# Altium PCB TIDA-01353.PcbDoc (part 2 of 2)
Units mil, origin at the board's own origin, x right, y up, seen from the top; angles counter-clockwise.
Board outline 6000 x 6000 mil, 2 copper layers (Top Layer, Bottom Layer), stack 61.6 mil thick; 250 components, 122 nets, 562 pads, 165 vias.
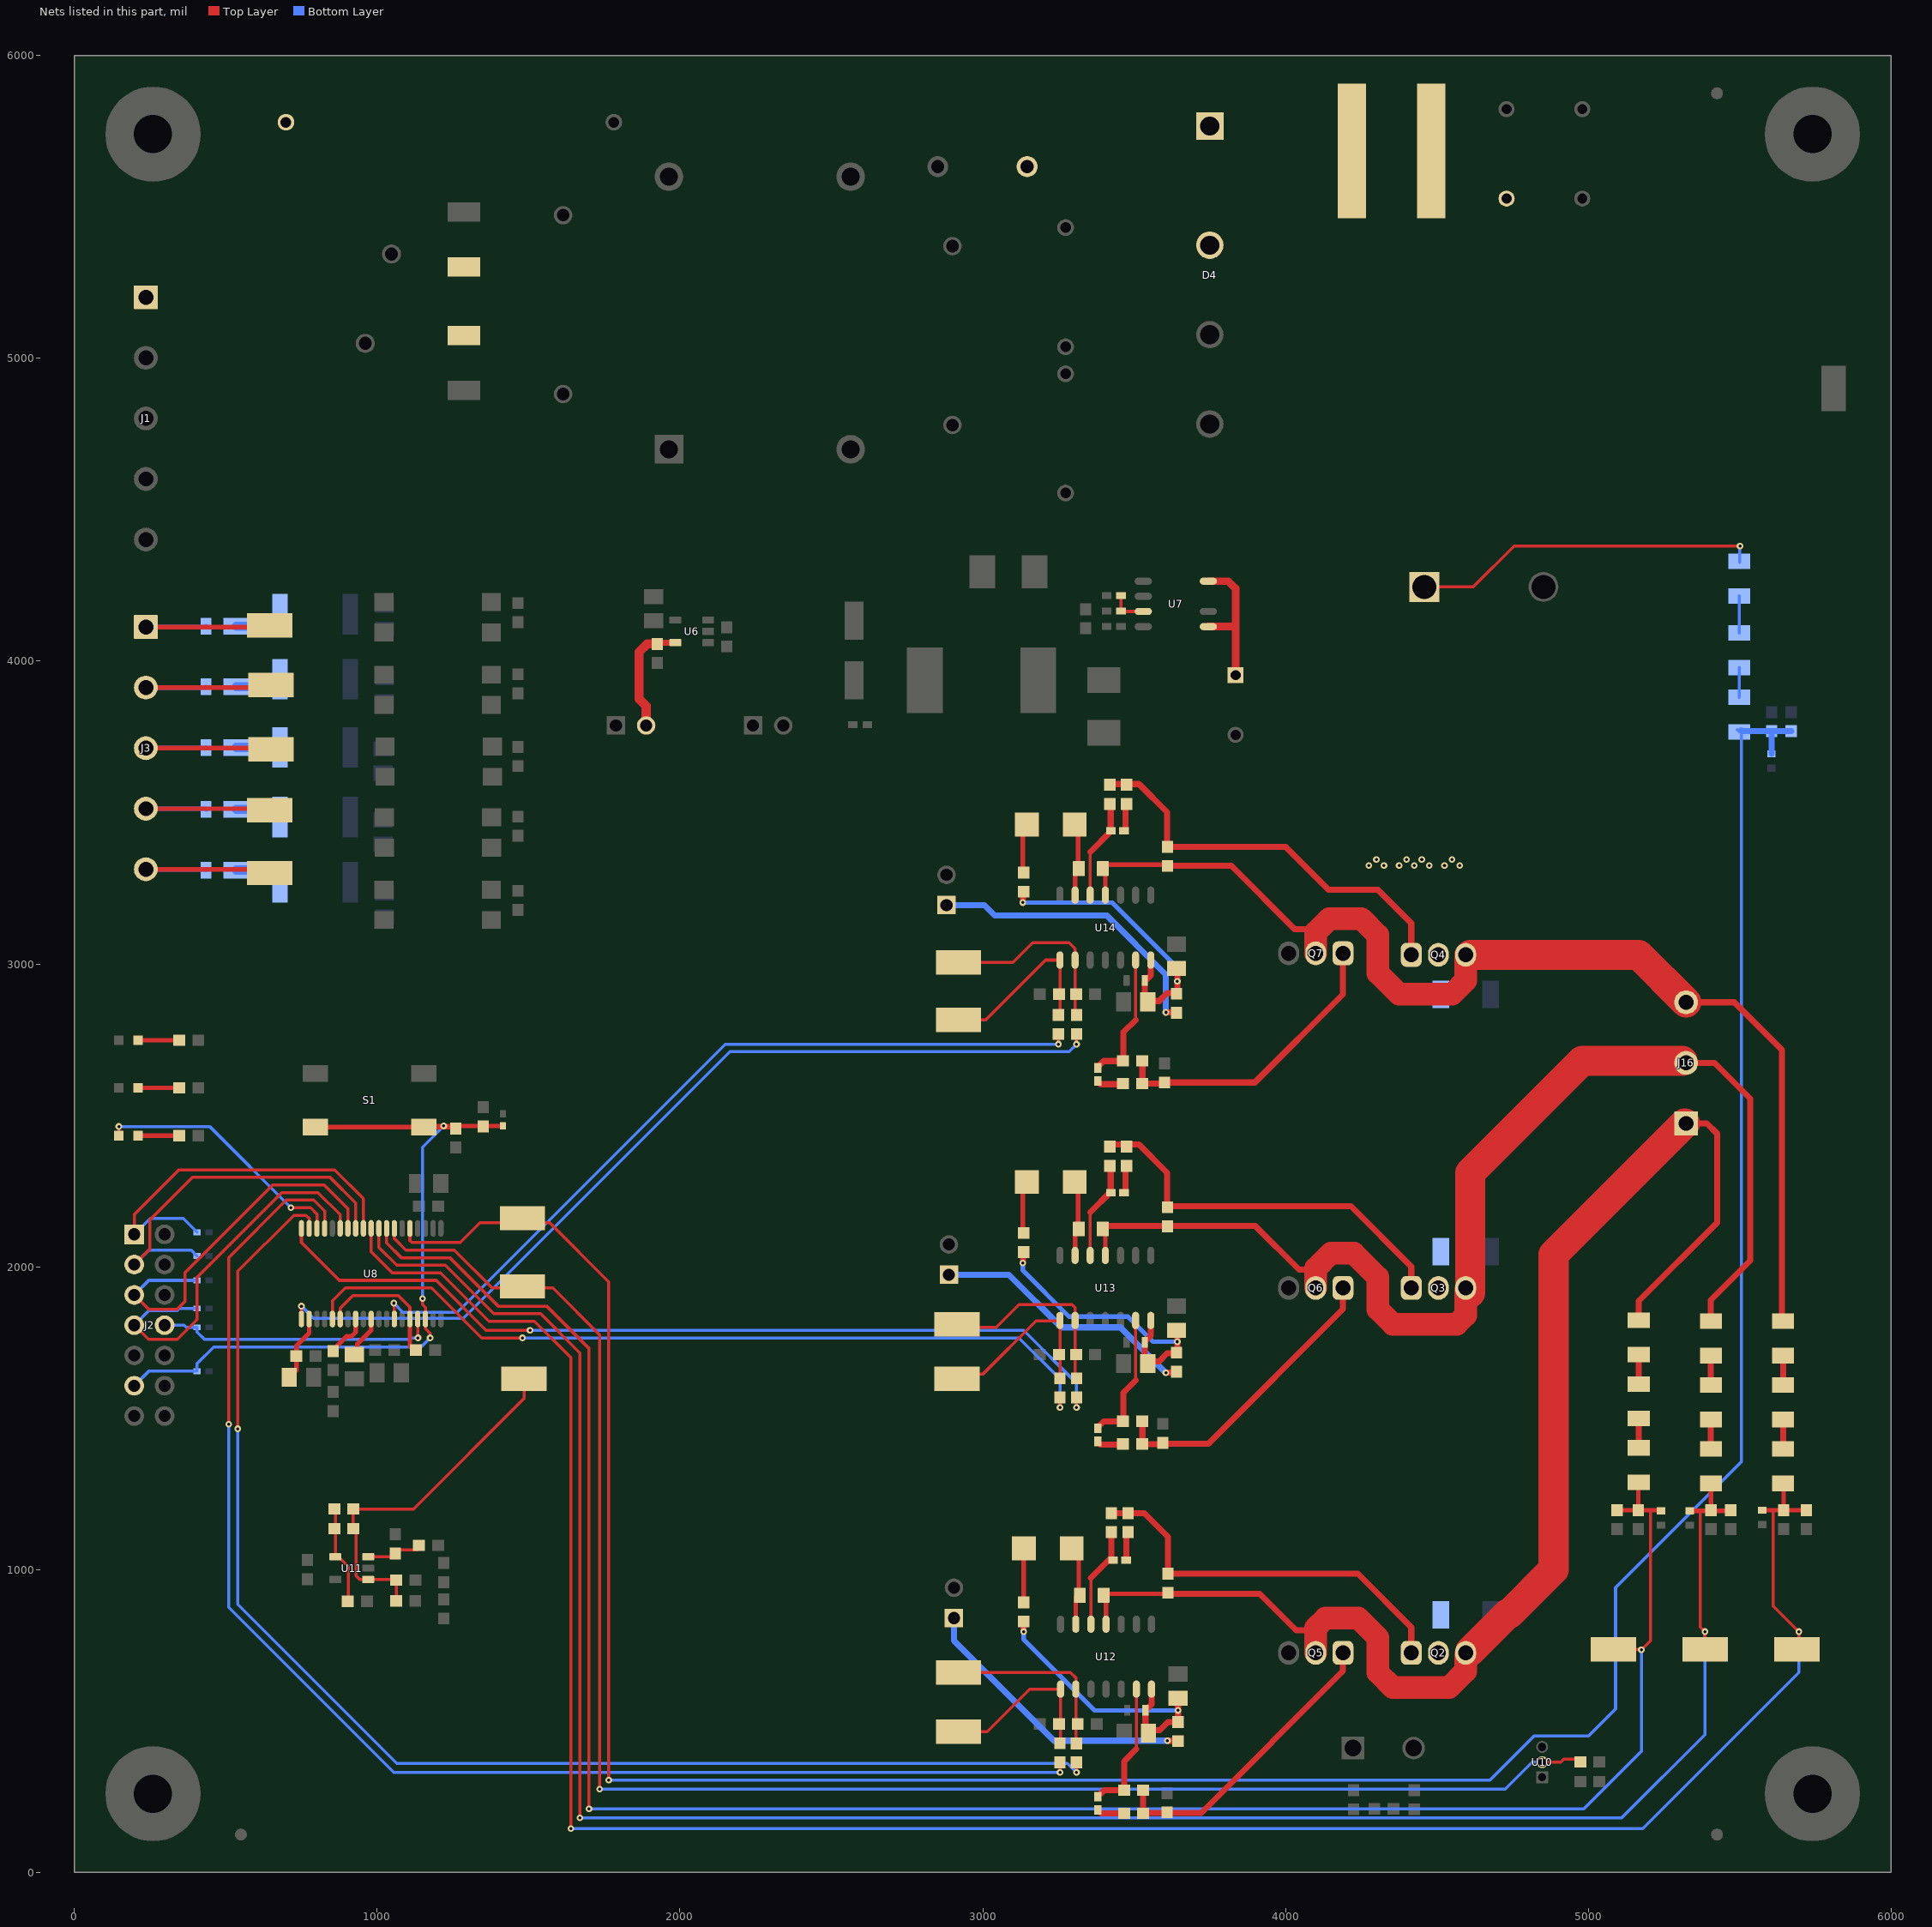
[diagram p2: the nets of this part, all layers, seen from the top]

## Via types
v1: diameter 22, hole 10, Top Layer to Bottom Layer, tented both sides, 165 vias

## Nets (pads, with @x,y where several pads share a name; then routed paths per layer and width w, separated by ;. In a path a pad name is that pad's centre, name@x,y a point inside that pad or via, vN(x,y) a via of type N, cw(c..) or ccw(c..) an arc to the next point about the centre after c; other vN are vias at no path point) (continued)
NetC19_1: C19.1 J4.2 U6.5 | length 385.1
  Top Layer w10: C19.1@1925,4056.5 C19.1@1929.53,4061.02
  Top Layer w20: C19.1@1929.53,4061.02 U6.5@1984.93,4061.02
  Top Layer w30: J4.2@1888.58,3787.4 1888.58,3851.42 1865,3875 1865,4030 1891.5,4056.5 C19.1@1925,4056.5
NetC26_1: C26.1 U8.29 | length 131.2
  Top Layer w15: C26.1@935,1715 935,1745 980.32,1790.32 U8.29@980.32,1827.44
NetC27_1: C27.1 C28.1 U8.21 | length 219.6
  Top Layer w15: C27.1@710,1635 733.5,1658.5 733.5,1738.5 775.59,1780.59 U8.21@775.59,1827.44
NetC37_1: C37.1 R34.1 R44.2 R55.2 TP17.1 U11.1 | length 1212.2
  Top Layer w10: R44.2@1063.07,896.65 1063.5,897.09 R55.2@1063.5,965 1061.17,967.33 U11.1@970.5,967.33 942.67,967.33 930,980 930,1127.68 920.31,1137.36 920.31,1195.31 925,1200 1120,1200 1485,1565 1485,1625.24 TP17.1@1480.31,1629.92
NetC37_2: C37.2 R34.2 R45.2 U11.4 | length 333.9
  Top Layer w10: R34.2@862.23,1211.19 862.23,1052.77 905,1010 R45.2@905,895
NetC46_1: C46.1 C50.1 C56.2 R56.1 R58.1 U12.7 | length 995.6
  Top Layer w15: C50.1@3537.32,480 C50.1@3547.32,470
  Top Layer w20: v1(3135,795) R56.1@3135,828.5 ; C50.1@3537.32,480 C46.1@3537.32,535 3557.32,555 U12.7@3557.32,605.16 ; C50.1@3547.32,470 3585,470 3611.5,496.5 R58.1@3645,496.5 C56.2@3645,570
  Bottom Layer w15: v1(3135,795) 3135,770 3370,535 v1(3645,535)
NetC47_1: C47.1 C51.1 C57.2 R57.1 R59.1 U13.7 | length 981.4
  Top Layer w20: v1(3132.68,2012.56) R57.1@3132.68,2046.06 ; C51.1@3535,1697.56 3535,1752.56 3555,1772.56 U13.7@3555,1822.72 ; C51.1@3545,1687.56 3582.68,1687.56 3609.18,1714.06 3642.68,1714.06 C57.2@3642.68,1787.56
  Bottom Layer w15: v1(3132.68,2012.56) 3132.68,1987.56 3285.24,1835 3480,1835 3562.44,1752.56 v1(3642.68,1752.56)
NetC48_1: C48.1 D20.1 U12.13 | length 272.9
  Top Layer w15: D20.1@3293.82,1078.74 3317.32,1055.24 3317.32,920 3307.32,910 U12.13@3307.32,819.72
NetC49_1: C49.1 D21.1 U13.13 | length 225.5
  Top Layer w15: U13.13@3305,2037.28 C49.1@3305,2127.56 ; C49.1@3315,2137.56 D21.1@3315,2272.8
NetC52_1: C52.1 R62.2 TP25.1 U12.1 | length 575
  Top Layer w10: TP25.1@2920,465 3015,465 3155.16,605.16 U12.1@3257.32,605.16 3257.32,428.81 R62.2@3255,426.5
NetC53_1: C53.1 R63.2 TP26.1 U13.1 | length 610.6
  Top Layer w10: TP26.1@2915,1630 2930,1645 3000,1645 3176.54,1821.54 U13.1@3255,1821.54 ; R63.2@3255,1631.5 U13.1@3255,1821.54 ; U13.1@3255,1822.72 U13.1@3255,1821.54
NetC54_1: C54.1 R68.2 TP29.1 U12.2 | length 618
  Top Layer w10: TP29.1@2920,645 2935,660 3290,660 3307.32,642.68 U12.2@3307.32,605.16 3307.32,428.53 R68.2@3309.57,426.28
NetC55_1: C55.1 R69.2 TP32.1 U13.2 | length 660.8
  Top Layer w10: TP32.1@2915,1800 3045,1800 3120,1875 3295,1875 3305,1865 U13.2@3305,1822.72 3305,1636.5 R69.2@3310,1631.49
NetC58_1: C58.1 C60.1 C66.2 R76.1 R77.1 U14.7 | length 993
  Top Layer w20: v1(3132.68,3202.56) R76.1@3132.68,3236.06 ; C60.1@3535,2887.56 3535,2942.56 3555,2962.56 U14.7@3555,3012.72 ; C60.1@3545,2877.56 3582.68,2877.56 3609.18,2904.06 3642.68,2904.06 C66.2@3642.68,2977.56
  Bottom Layer w15: v1(3132.68,3202.56) 3427.44,3202.56 3642.68,2987.32 v1(3642.68,2942.56)
NetC59_1: C59.1 D26.1 U14.13 | length 225.5
  Top Layer w15: U14.13@3305,3227.28 C59.1@3305,3317.56 ; C59.1@3315,3327.56 D26.1@3315,3462.8
NetC64_1: C64.1 R79.2 TP35.1 U14.1 | length 606.9
  Top Layer w10: TP35.1@2920,2815 3010,2815 3207.72,3012.72 U14.1@3255,3012.72 ; R79.2@3255,2821.5 U14.1@3255,3011.54
NetC65_1: C65.1 R82.2 TP37.1 U14.2 | length 643.7
  Top Layer w10: TP37.1@2920,3005 3100,3005 3165,3070 3285,3070 3305,3050 U14.2@3305,3012.72 R82.2@3305,2826.5
NetD1_1: D1.1 R2.1 | length 139.8
  Bottom Layer w30: D1.1@535.2,3310 R2.1@675,3310
NetD2_1: D2.1 R4.1 | length 139.8
  Bottom Layer w30: D2.1@535.2,3510 R4.1@675,3510
NetD3_1: D3.1 R7.1 | length 143.7
  Bottom Layer w30: D3.1@535.2,3715 R7.1@678.86,3715
NetD4_1: D4.1 L1.1
NetD4_2: D4.2 RT1.2
NetD5_1: D5.1 R10.1 | length 139.8
  Bottom Layer w30: D5.1@535.2,3915 R10.1@675,3915
NetD6_1: D6.1 R12.1 | length 139.8
  Bottom Layer w30: D6.1@535.2,4115 R12.1@675,4115
NetD13_1: D13.1 U8.17 | length 855.5
  Top Layer w10: v1(147.05,2463.19) D13.1@147.05,2433.07 D13.1@150,2430.12 ; v1(715,2195) 780,2195 801.18,2173.82 U8.17@801.18,2126.66
  Bottom Layer w10: v1(147.05,2463.19) 446.81,2463.19 v1(715,2195)
NetD13_2: D13.2 R26.2 | length 136.4
  Top Layer w15: D13.2@210.04,2433.07 R26.2@346.46,2433.07
NetD14_2: D14.2 R29.1 | length 136.4
  Top Layer w15: D14.2@210.04,2748.03 R29.1@346.46,2748.03
NetD15_2: D15.2 R27.2 | length 136.4
  Top Layer w15: D15.2@210.04,2590.55 R27.2@346.46,2590.55
NetD20_2: D20.2 R56.2 | length 187.8
  Top Layer w15: R56.2@3135,891.5 3135,1077.4 D20.2@3136.34,1078.74
NetD21_2: D21.2 R57.2 | length 185.9
  Top Layer w15: R57.2@3132.68,2109.06 D21.2@3132.68,2294.96
NetD22_1: D22.1 R60.1 U12.12 | length 331.8
  Top Layer w10: U12.12@3357.32,819.72 3357.32,972.32
  Top Layer w20: 3357.32,972.32 3425,1040 R60.1@3425,1123.5
NetD22_2: D22.2 R64.1 | length 95
  Top Layer w10: R64.1@3473.75,1117.25 R64.1@3480,1123.5
  Top Layer w20: D22.2@3473.75,1031.11 R64.1@3473.75,1117.25
NetD23_1: D23.1 R61.1 U13.12 | length 331.8
  Top Layer w10: U13.12@3355,2037.28 3355,2179.87
  Top Layer w20: 3355,2179.87 3422.68,2247.56 R61.1@3422.68,2341.06
NetD23_2: D23.2 R65.1 | length 86.1
  Top Layer w20: D23.2@3471.43,2248.67 R65.1@3471.43,2334.81
NetD24_1: D24.1 R72.1 U12.6 | length 442.9
  Top Layer w10: 3507.32,407.32 U12.6@3507.32,605.16
  Top Layer w20: D24.1@3379.84,250 3401.5,271.65 R72.1@3466.84,271.65 ; R72.1@3466.84,275 3466.84,366.84 3507.32,407.32
NetD24_2: D24.2 R70.1 | length 91.8
  Top Layer w20: D24.2@3379.84,206.69 3391.32,195.22 R70.1@3466.84,195.22
NetD25_1: D25.1 R73.1 U13.6 | length 442.9
  Top Layer w10: 3505,1624.88 U13.6@3505,1822.72
  Top Layer w20: D25.1@3377.53,1467.56 3399.18,1489.21 R73.1@3464.53,1489.21 ; R73.1@3464.53,1492.56 3464.53,1584.4 3505,1624.88
NetD25_2: D25.2 R71.1 | length 91.8
  Top Layer w20: D25.2@3377.53,1424.25 3389,1412.78 R71.1@3464.53,1412.78
NetD26_2: D26.2 R76.2 | length 185.9
  Top Layer w15: R76.2@3132.68,3299.06 D26.2@3132.68,3484.96
NetD27_1: D27.1 R78.1 U14.12 | length 331.8
  Top Layer w10: U14.12@3355,3227.28 3355,3369.88
  Top Layer w20: 3355,3369.88 3422.68,3437.56 R78.1@3422.68,3531.06
NetD27_2: D27.2 R80.1 | length 86.1
  Top Layer w20: D27.2@3471.43,3438.67 R80.1@3471.43,3524.81
NetD28_1: D28.1 R84.1 U14.6 | length 442.9
  Top Layer w10: 3505,2814.88 U14.6@3505,3012.72
  Top Layer w20: D28.1@3377.53,2657.56 3399.18,2679.21 R84.1@3464.53,2679.21 ; R84.1@3464.53,2682.56 3464.53,2774.4 3505,2814.88
NetD28_2: D28.2 R83.1 | length 91.8
  Top Layer w20: D28.2@3377.53,2614.25 3389,2602.78 R83.1@3464.53,2602.78
NetF1_2: F1.2 J1.1
NetJ12_1: J12.1 R58.2 | length 952.3
  Top Layer w10: v1(3610,435) v1@3611.5,433.5
  Top Layer w20: v1(3610,435) R58.2@3643.5,435
  Bottom Layer w20: J12.1@2905,840 2905,765 3235,435 v1(3610,435)
NetJ13_1: J13.1 R59.2 | length 887.2
  Top Layer w10: R59.2@3636.49,1650 R59.2@3640,1653.5
  Top Layer w20: v1(3605,1650) R59.2@3636.49,1650
  Bottom Layer w20: J13.1@2888.31,1973.62 3086.38,1973.62 3260,1800 3455,1800 v1(3605,1650)
NetJ15_1: J15.1 R77.2 | length 978
  Top Layer w20: v1(3605,2840) R77.2@3638.5,2840
  Bottom Layer w20: J15.1@2880.43,3194.09 3005.91,3194.09 3040,3160 3410,3160 3605,2965 v1(3605,2840)
NetR5_1: R5.1 R8.2
NetR13_1: R13.1 R14.2 U7.3 | length 125.4
  Top Layer w10: R14.2@3456.69,4216.54 R13.1@3456.69,4165.35 3458.07,4163.98 U7.3@3530.33,4163.98
NetR32_1: R32.1 U8.27 | length 148.4
  Top Layer w15: R32.1@850,1721.5 898.5,1770 915,1770 929.13,1784.14 U8.27@929.13,1827.44
NetR35_1: R35.1 R41.2 | length 96.8
  Top Layer w20: R41.2@5166.73,1612.94 R35.1@5166.73,1709.71
NetR36_1: R36.1 R42.2 | length 96.8
  Top Layer w20: R42.2@5404.69,1609.73 R36.1@5404.69,1706.5
NetR37_1: R37.1 R43.2 | length 96.8
  Top Layer w20: R43.2@5643.3,1609.73 R37.1@5643.3,1706.5
NetR38_1: R38.1 R40.2 | length 122
  Bottom Layer w10: R40.2@5498.35,4093.11 R38.1@5498.35,4215.16
NetR39_2: R39.2 R50.2 U11.3 | length 172.1
  Top Layer w10: U11.3@970.5,1042.14 1044.26,1042.14 R50.2@1060.74,1058.62 ; R50.2@1060,1065 R39.2@1135,1065
NetR40_1: R40.1 R46.2 | length 98.4
  Bottom Layer w10: R46.2@5498.35,3880.51 R40.1@5498.35,3978.94
NetR41_1: R41.1 R47.2 | length 96.8
  Top Layer w20: R47.2@5166.73,1401.99 R41.1@5166.73,1498.77
NetR42_1: R42.1 R48.2 | length 96.8
  Top Layer w20: R48.2@5404.69,1398.78 R42.1@5404.69,1495.55
NetR43_1: R43.1 R49.2 | length 96.8
  Top Layer w20: R49.2@5643.3,1398.78 R43.1@5643.3,1495.55
NRST: C24.1 J2.11 R30.1 S1.3 S1.4 U8.36 U15.1 U20.2 | length 2502.3
  Top Layer w10: v1(1150,1895) 1150,1875 1159.45,1865.55 U8.36@1159.45,1827.44 1159.45,1795.55 1175,1780 v1(1175,1765)
  Top Layer w15: S1.3@780,2461.42 S1.3@795.87,2461.42 S1.4@1154.13,2461.42 R30.1@1249.13,2461.42 ; S1.4@1170.39,2465 v1(1220,2465) C24.1@1345,2465 ; C24.1@1353.03,2465 U20.2@1415,2465
  Bottom Layer w10: J2.11@198.03,1607.09 245.95,1655 U15.1@405.32,1655 405.32,1680.32 460,1735 1145,1735 v1(1175,1765) ; v1(1150,1895) 1150,2395 v1(1220,2465)
OC_FLT: R31.2 U8.25 U8.34 | length 447.1
  Top Layer w10: U8.25@877.95,1827.44 877.95,1862.95 920,1905 1070,1905 1108.27,1866.73 U8.34@1108.27,1827.44
  Top Layer w15: U8.34@1108.27,1827.44 1108.27,1738.19 R31.2@1122.05,1724.41
PHU: C48.2 J16.1 Q2.3 Q5.2 R35.2 R66.1 U12.11 | length 4556.9
  Top Layer w15: U12.11@3407.32,819.72 3407.32,910 3397.32,920 R66.1@3611.49,920
  Top Layer w20: R66.1@3611.5,920 3915,920 4035,800 4095,800 ; R35.2@5166.73,1823.89 5166.73,1886.73 5425,2145 5425,2440 5391.77,2473.23 J16.1@5322.83,2473.23
  Top Layer w75: Q5.2@4100,725 4100,808 4132,840 4240,840 4305,775 4305,660 4355,610 4540,610 4594.76,664.76 Q2.3@4594.76,720
  Top Layer w100: Q2.3@4610,730 4735,855 ; 4740,855 4885,1000 4885,2040 J16.1@5318.23,2473.23
PHU_FB: C41.1 D16.2 R47.1 R51.2 TP19.1 U8.8 | length 7075.1
  Top Layer w10: U8.8@1031.5,2126.66 1031.5,2078.5 1080,2030 1240,2030 1400,1870 1560,1870 1700,1730 v1(1700,210) ; TP19.1@5082.68,736.65 5176.65,736.65 5205,765 5205,1196.02
  Top Layer w15: C41.1@5091.93,1196.02 5239.53,1196.02 D16.2@5240,1196.5 ; R51.2@5165,1196.5 5165,1286.09 R47.1@5166.73,1287.82
  Bottom Layer w10: v1(1700,210) 4985,210 5175,400 v1(5175,735)
PHV: C49.2 J16.2 Q3.3 Q6.2 R36.2 R67.1 U13.11 | length 3971
  Top Layer w15: U13.11@3405,2037.28 C49.2@3405,2127.56
  Top Layer w20: C49.2@3395,2135 3900,2135 4045,1990 4080,1990 ; J16.2@5322.83,2673.23 5416.77,2673.23 5535,2555 5535,2020 5404.69,1889.69 R36.2@5404.69,1820.67
  Top Layer w75: Q6.2@4100,1930 4100,1995 4150,2045 4225,2045 4305,1965 4305,1860 4355,1810 4565,1810 4594.76,1839.76 Q3.3@4594.76,1925
  Top Layer w100: Q3.3@4610,1915 4610,2310 4980,2680 J16.2@5311.06,2680
PHV_FB: C42.1 D17.2 R48.1 R52.2 TP20.1 U8.9 | length 7263.1
  Top Layer w10: U8.9@1005.91,2126.66 1005.91,2064.09 1065,2005 1225,2005 1385,1845 1540,1845 1670,1715 v1(1670,180) ; 5370,1193.62 5370,810 5385.83,794.17 TP20.1@5385.83,736.65
  Top Layer w15: D17.2@5335,1193.62 5467.12,1193.62 C42.1@5470,1196.5 ; R48.1@5404.69,1284.61 5405,1284.29 R52.2@5405,1196.5
  Bottom Layer w10: v1(1670,180) 5110,180 5385,455 v1(5385,795)
PHW: C59.2 J16.3 Q4.3 Q7.2 R37.2 R81.1 U14.11 | length 3872.1
  Top Layer w15: C59.2@3395,3327.56 3546.18,3327.56 3607.44,3327.56 R81.1@3611,3324 ; U14.11@3405,3227.28 C59.2@3405,3317.56 ; Q7.2@4100,3045 4100,3115
  Top Layer w20: R81.1@3611,3324 3821,3324 4030,3115 4100,3115 ; J16.3@5322.83,2873.23 5481.77,2873.23 5640,2715 R37.2@5640,1820.67
  Top Layer w75: Q7.2@4100,3035 4100,3105 4145,3150 4250,3150 4305,3095 4305,2970 4375,2900 4550,2900 4594.76,2944.76 Q4.3@4594.76,3030
  Top Layer w100: Q4.3@4610,3030 5166.06,3030 J16.3@5322.83,2873.23
PHW_FB: C43.1 D18.2 R49.1 R53.2 TP21.1 U8.10 | length 7571.9
  Top Layer w10: U8.10@980.32,2126.66 980.32,2049.68 1050,1980 1210,1980 1370,1820 1520,1820 1640,1700 v1(1640,145) ; 5610,1196.02 5610,880 v1(5695,795) 5695,742.68 TP21.1@5688.98,736.65
  Top Layer w15: D18.2@5573.97,1196.02 5719.53,1196.02 C43.1@5720,1196.5 ; R49.1@5643.3,1284.61 5645,1282.91 R53.2@5645,1196.5
  Bottom Layer w10: v1(1640,145) 5180,145 5695,660 v1(5695,795)
PWM_UB: R68.1 U8.18 | length 4487.7
  Top Layer w10: v1(540,1465) 540,1985 725,2170 765,2170 775.59,2159.41 U8.18@775.59,2126.66 ; R68.1@3309.57,363.29 3309.57,330.43 v1(3310,330)
  Bottom Layer w10: v1(540,1465) 540,885 1065,360 3280,360 v1(3310,330) v1@3310,325
PWM_UT: R62.1 U8.16 | length 4626.5
  Top Layer w10: v1(510,1480) 510,2030 700,2220 790,2220 826.77,2183.23 U8.16@826.77,2126.66 ; v1(3255,330) R62.1@3255,363.51
  Bottom Layer w10: v1(510,1480) 510,875 1055,330 v1(3255,330)
PWM_VB: R69.1 U8.19 | length 2917.8
  Top Layer w10: U8.19@750,2126.66 750,2080 875,1955 1195,1955 1360,1790 v1(1505,1790) ; v1(3310,1535) R69.1@3310,1568.5
  Bottom Layer w10: v1(1505,1790) 3135,1790 3310,1615 v1(3310,1535) v1@3310,1530
PWM_VT: R63.1 U8.24 | length 2738
  Top Layer w10: U8.24@852.36,1827.44 852.36,1887.36 895,1930 1180,1930 1345,1765 v1(1480,1765) ; v1(3255,1535) R63.1@3255,1568.5
  Bottom Layer w10: v1(1480,1765) 3120,1765 3255,1630 v1(3255,1535) v1@3255,1530
PWM_WB: R82.1 U8.20 | length 3027.5
  Top Layer w10: U8.20@750,1827.44 v1(750,1870) ; v1(3310,2735) R82.1@3310,2768.5
  Bottom Layer w10: v1(750,1870) 790,1830 1285,1830 2165,2710 3285,2710 v1(3310,2735)
PWM_WT: R79.1 U8.32 | length 2660.9
  Top Layer w10: v1(1055,1880) 1057.09,1877.91 U8.32@1057.09,1827.44 ; v1(3250,2735) R79.1@3250,2768.5
  Bottom Layer w10: v1(1055,1880) 1085,1850 1265,1850 2150,2735 v1(3250,2735)
SIGNAL_PIN1: D6.2 J3.1 TP5.1 | length 603.5
  Top Layer w15: J3.1@236.22,4112.6 TP5.1@640.16,4112.6
  Bottom Layer w15: J3.1@236.22,4112.6 432.4,4112.6 D6.2@434.8,4115
SIGNAL_PIN2: D5.2 J3.2 TP6.1 | length 604.3
  Top Layer w15: J3.2@236.22,3912.6 TP6.1@640.94,3912.6
  Bottom Layer w15: J3.2@236.22,3912.6 432.4,3912.6 D5.2@434.8,3915
SIGNAL_PIN3: D3.2 J3.3 TP7.1 | length 609
  Top Layer w15: J3.3@236.22,3712.6 TP7.1@645.67,3712.6
  Bottom Layer w15: J3.3@236.22,3712.6 432.4,3712.6 D3.2@434.8,3715
SIGNAL_PIN4: D2.2 J3.4 TP8.1 | length 604.4
  Top Layer w15: J3.4@236.22,3512.6 TP8.1@640.95,3512.6
  Bottom Layer w15: J3.4@236.22,3512.6 432.2,3512.6 D2.2@434.8,3510
SIGNAL_PIN5: D1.2 J3.5 TP9.1 | length 580.8
  Top Layer w15: J3.5@236.22,3312.6 TP9.1@617.4,3312.6
  Bottom Layer w15: J3.5@236.22,3312.6 432.2,3312.6 D1.2@434.8,3310
TCK: J2.7 U8.14 U16.1 | length 1288.2
  Top Layer w10: J2.7@198.03,1807.09 245.12,1760 340,1760 405,1825 405,1965 685,2245 805,2245 877.95,2172.05 U8.14@877.95,2126.66
  Bottom Layer w10: J2.7@198.03,1807.09 245.95,1855 340,1855 347.2,1862.2 U16.1@405.51,1862.2
TDI: J2.3 U8.12 U18.1 | length 1261.1
  Top Layer w10: J2.3@198.03,2007.09 250,2059.05 250,2155 390,2295 845,2295 929.13,2210.86 U8.12@929.13,2126.66
  Bottom Layer w10: J2.3@198.03,2007.09 245.95,2055 385.94,2055 U18.1@405.51,2035.43
TDO: J2.1 U8.11 U19.1 | length 1269.8
  Top Layer w10: J2.1@198.03,2107.09 198.03,2173.03 345,2320 860,2320 954.72,2225.28 U8.11@954.72,2126.66
  Bottom Layer w10: J2.1@198.03,2107.09 250.95,2160 359.69,2160 U19.1@405.51,2114.17
TEMP_SENSE: C36.2 TP15.1 U8.7 U10.2 | length 5626.8
  Top Layer w10: U8.7@1057.09,2126.66 1057.09,2092.91 1095,2055 1255,2055 1380,1930 1580,1930 1735,1775 v1(1735,275) ; U10.2@4847.44,364.25 4909.25,364.25 4918.76,373.76 C36.2@4977.51,373.76
  Bottom Layer w10: v1(1735,275) 4695,275 4725,275 4814.25,364.25 U10.2@4847.44,364.25
TEST: J2.8 U8.35 U9.1 | length 927.5
  Top Layer w10: U8.35@1133.86,1827.44 1133.86,1776.14 v1@1140,1770
  Bottom Layer w10: J2.8@298.03,1807.09 362.91,1807.09 370,1800 U9.1@405.32,1800 405.32,1784.68 430,1760 1105,1760 1110,1765 v1(1135,1765)
TMS: J2.5 U8.13 U17.1 | length 1275
  Top Layer w10: J2.5@198.03,1907.09 245.12,1860 340,1860 365,1885 365,1980 655,2270 825,2270 903.55,2191.45 U8.13@903.55,2126.66
  Bottom Layer w10: J2.5@198.03,1907.09 245.95,1955 U17.1@405.32,1955
UB: Q5.1 R70.2 R72.2 R74.2 | length 991.1
  Top Layer w20: R72.2@3529.84,271.65 R70.2@3529.84,195.22 3531.47,196.85 3721.85,196.85 4189.76,664.76 Q5.1@4189.76,725
UT: Q2.1 R60.2 R64.2 R66.2 | length 1297.5
  Top Layer w20: R60.2@3425,1186.5 R64.2@3480,1186.5 3533.5,1186.5 3611.5,1108.5 R66.2@3611.49,986.5 4238.5,986.5 4415.24,809.76 Q2.1@4415.24,730
VB: Q6.1 R71.2 R73.2 R75.2 | length 989.5
  Top Layer w20: R71.2@3527.52,1412.78 R73.2@3527.52,1489.21 ; R71.2@3529.15,1414.41 R75.2@3606.47,1414.41 ; R75.2@3608.51,1415 3745,1415 4189.76,1859.76 Q6.1@4189.76,1930
VDC_FB: C44.1 D19.2 R46.1 R54.2 TP22.1 U8.5 | length 9529.4
  Top Layer w10: U8.5@1108.27,2126.66 1108.27,2086.73 1115,2080 1275,2080 1340,2145 1570,2145 1765,1950 v1(1765,305)
  Bottom Layer w10: v1(1765,305) 4675,305 4820,450 5000,450 5090,540 5090,940 5505,1355 R46.1@5505,3771.65 ; R46.1@5491.18,3773.5 R46.1@5498.35,3766.34
  Bottom Layer w20: R46.1@5505,3771.65 5508.15,3768.5 C44.1@5670,3768.5 ; D19.2@5605,3693.62 R54.2@5605,3768.5
VDC_LINK: C3.1 C7.1 C17.1 C61.1 C62.1 C63.1 L1.2 Q2.2 Q3.2 Q4.2 R38.2 U7.5 U7.8 | length 1630.4
  Top Layer w10: C7.1@4458.15,4245 4620,4245 4755,4380 v1(5500.67,4380)
  Top Layer w25: U7.5@3744.9,4113.98 3831.02,4113.98 3835,4110 ; U7.8@3744.9,4263.98 3811.02,4263.98 3835,4240 3835,4110 ; C17.1@3835,3953.43 3835,4110
  Bottom Layer w10: R38.2@5500,4326.65 5500,4379.33 v1(5500.67,4380)
  other v1: 4275,3325 4325,3325 4375,3325 4425,3325 4475,3325 4525,3325 4575,3325 4300,3345 4400,3345 4450,3345 4550,3345
VT: Q3.1 R61.2 R65.2 R67.2 | length 1291.2
  Top Layer w20: R61.2@3422.68,2404.05 3515.95,2404.05 3609.18,2310.82 R67.2@3609.18,2204.05 ; R67.2@3609.18,2200 4216,2200 4415.24,2000.76 Q3.1@4415.24,1930
WB: Q7.1 R83.2 R84.2 R85.2 | length 999.4
  Top Layer w20: R83.2@3527.52,2602.78 R84.2@3527.52,2679.21 ; R83.2@3529.15,2604.41 R85.2@3606.46,2604.41 ; R85.2@3600,2608.5 3898.5,2608.5 4189.76,2899.76 Q7.1@4189.76,3035
WT: Q4.1 R78.2 R80.2 R81.2 | length 1346.2
  Top Layer w20: R78.2@3422.68,3594.06 3515.94,3594.06 3609.18,3500.82 R81.2@3609.18,3394.06 ; R81.2@3610,3386.5 4000.5,3386.5 4142,3245 4305,3245 4415.24,3134.76 Q4.1@4415.24,3030
pads on no net: FID1.1 FID2.1 FID3.1 FID4.1 FID5.1 FID6.1 H1.1 H2.1 H3.1 H4.1 J1.4 J2.2 J2.6 J2.10 J2.12 J2.13 J2.14 SH-J4.0 SH-J5.0 SH-J12.0 SH-J13.0 SH-J15.0 U7.6 U8.2 U8.3 U8.26 U12.8 U12.9 U12.10 U12.14 U13.8 U13.9 U13.10 U13.14 U14.8 U14.9 U14.10 U14.14

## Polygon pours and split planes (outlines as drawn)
NetC6_2 on Top Layer "Top Layer-No Net" (solid, remove dead copper, pour order 109): 2475,4880 3330,4880 3600,5150 3810,5150 3810,5025 3810,4980 3780,4950 3330,4500 3300,4500 3250,4500 2475,4500
GND on Top Layer "Top Layer-No Net" (solid, remove dead copper, pour order 112): 50,3025 1350,3025 1350,4325 2735,4325 2852.5,4442.5 3342.5,4442.5 3800,4900 3875,4900 4925,4900 4925,5450 4925,5525 4925,5555 5395,5555 5525,5425 5950,5425 5950,500 5555,500 5450,395 4880,395 4810,395 4790,375 4275,375 725,375 500,375 50,825
NetF1_2 on Top Layer "Top Layer-No Net" (solid, remove dead copper, pour order 107): 175,5275 500,5600 550,5650 550,5800 550,5875 850,5875 850,5250 725,5125 700,5100 175,5100
NetC5_2 on Top Layer "Top Layer-No Net" (solid, remove dead copper, pour order 110): 200,4900 675,4900 775,5000 900,5125 1000,5125 1025,5125 1175,4975 1675,4975 1975,4975 2075,4875 2075,4550 1575,4550 1525,4600 1500,4625 1325,4625 375,4625 325,4675 300,4700 175,4700 175,4900
NetC5_1 on Top Layer "Top Layer-No Net" (solid, remove dead copper, pour order 108): 950,5300 950,5400 950,5450 1100,5600 1125,5625 1350,5850 1650,5850 1850,5850 2050,5650 2050,5400 1350,5400 1200,5400 1100,5300
NetC4_1 on Top Layer "Top Layer-No Net" (solid, remove dead copper, pour order 106): 2475,5750 2700,5750 2875,5750 3050,5575 3100,5525 3300,5525 3350,5475 3350,5250 2475,5250
NetD4_1 on Top Layer "Top Layer-No Net" (solid, remove dead copper, pour order 105): 3695,5925 4275,5925 4275,5450 4000,5450 3970,5450 3695,5725
NetD4_2 on Top Layer "Top Layer-No Net" (solid, remove dead copper, pour order 104): 3075,5800 3575,5800 3750,5625 3810,5565 3810,5300 3625,5300 3400,5525 3350,5575 3275,5575 3125,5575 3075,5625
VDC_LINK on Top Layer "Top Layer-No Net" (solid, remove dead copper, pour order 111): 3900,4730 3900,4020 3860,3980 3805,3980 3805,3887.5 3900,3792.5 3900,3555 4150,3305 4610,3305 4610,4290 4850,4530 4850,5275 4850,5425 4850,5625 4550,5925 4400,5925 4400,5230
GND on Bottom Layer "Top Layer-No Net" (solid, remove dead copper, pour order 116): 50,3025 1350,3025 1350,4325 2735,4325 2855,4445 3345,4445 3775,4875 4142.5,5242.5 4642.5,5242.5 4955,5555 5395,5555 5425,5525 5525,5425 5950,5425 5950,500 4850,500 4675,325 4325,325 3875,325 925,325 50,1200
E_GND on Bottom Layer "Top Layer-No Net" (solid, remove dead copper, pour order 115): 175,5100 725,5100 750,5100 875,4975 1000,4975 1200,5175 1275,5250 1322.5,5297.5 3272.5,5297.5 3362.5,5387.5 3362.5,5497.5 3565,5700 4050,5700 4225,5875 4275,5925 4750,5925 5050,5925 5050,5785 4845,5785 4817.5,5757.5 4532.5,5757.5 4325,5550 4275,5500 4217.5,5442.5 3687.5,5442.5 3652.5,5407.5 3652.5,5152.5 3400,4900 3175,4900 2000,4900 1925,4975 1625,4975 1600,4975 1525,4900 1350,4725 1000,4725 475,4725 300,4900 175,4900
VDC_LINK on Bottom Layer "Top Layer-No Net" (solid, remove dead copper, pour order 113): 4605,3360 4245,3360 4245,3200 4245,700 4345,600 4495,600 4570,675 4570,3075 4595,3100 4605,3100 4605,3250
EMT on Bottom Layer "Top Layer-No Net" (solid, remove dead copper, pour order 114): 4050,3100 4050,675 4130,595 4295,595 4295,350 4275,350 4000,350 3825,350 3725,450 3725,575 3725,2875 3950,3100

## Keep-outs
Keep-Out Layer:
  lines w10: -5,0 ccw(c0,0) 0,-5 ; -5,0 ccw(c0,0) 0,-5 ; -5,0 -5,6000 ; -5,6000 cw(c0,6000) 0,6005 ; -5,6000 cw(c0,6000) 0,6005 ; 0,-5 6000,-5 ; 0,6005 6000,6005 ; 6000,-5 ccw(c6000,0) 6005,0 ; 6000,-5 ccw(c6000,0) 6005,0 ; 6000,6005 cw(c6000,6000) 6005,6000 ; 6000,6005 cw(c6000,6000) 6005,6000 ; 6005,0 6005,6000
  text ".Layer_Name" at 577,-858.49 h60

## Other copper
Top Layer:
  rectangle net NetR5_1: 1225,5050 1350,5325
  rectangle net GND: 3510,4210 3550,4265
  rectangle net NetC15_1: 2545,3875 2865,4000
  rectangle net NetC13_2: 3125,3870 3455,4000
  rectangle net NetC15_1: 2305,3745 2585,3835
  rectangle net NetC15_1: 2515,3745 2585,4000
  text ".Layer_Name" at 577,-858.49 h60
Bottom Layer:
  pour cut-out: 5430,4425 5430,3705 5710,3705 5710,3815 5580,3815 5570,3825 5570,4425
  text ".Layer_Name" at 577,-858.49 h60

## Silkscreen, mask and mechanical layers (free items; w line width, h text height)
Top Overlay:
  region: 2501.42,426.02 2201.42,426.02 2201.42,326.02 2501.42,326.02
  lines w10: 0,2988.19 1460.63,2988.19 1610.24,2838.58 1610.24,760 ; 0,3070.87 1507.87,3070.87 1507.87,4555.12 1503.94,4559.06 602.36,4559.06 602.36,4267.72 ; 0,4267.72 551.18,4267.72 551.18,5326.77 551.18,5476.38 0,5476.38 ; 704.72,1779.53 808.25,1779.53 834.68,1753.1 ; 959.68,822.4 1002.99,822.4 1002.99,932.64 1002.99,964.13 1014.8,975.94 1030.55,975.94 ; 1625.98,4318.9 2732.28,4318.9 2811.02,4397.64 3361.14,4397.64 3597.36,4397.64 3752.36,4397.64 4025,4125 4025,3975 4400,3600 5935,3600 ; 2687.52,65 2687.52,1472.44 ; 2690,65 3758.39,65 3758.39,196.85 3758.39,3637.8 2687.52,3637.8 2687.52,2885.83 ; 2695.39,161.42 2793.82,161.42 ; 2695.39,1255.91 2797.76,1255.91 ; 2695.39,2472.44 2797.76,2472.44 ; 3096.97,1255.91 3683.58,1255.91 3758.39,1330.71 ; 3112.72,157.48 3317.44,157.48 ; 3116.65,2472.44 3636.34,2472.44 3679.65,2472.44 3758.39,2551.18 ; 3472.44,5724.41 3472.44,5826.77 ; 3551.18,5614.17 3685,5614.17 ; 3905,555 4750,555 ; 4650,90 4650,555 ; 5194.61,4546.06 5383.58,4735.04 5383.58,4904.33 ; 1456.69,2362.2 720.47,2362.2 720.47,2814.96 1456.69,2814.96 1456.69,2362.2 ; 1456.69,2362.2 1456.69,2362.2 ; 2687.52,1472.44 2687.52,2885.83 ; 2687.52,1472.44 2533.98,1625.98 2533.98,2732.28 2687.52,2885.83 ; 5383.58,4904.33 5383.58,5030.32 4686.73,5030.32 4686.73,4908.27 5013.5,4908.27 5379.65,4908.27 5383.58,4904.33 ; 551.18,759.84 1476.38,759.84 1476.38,1314.96 551.18,1314.96 551.18,759.84 ; 2694.84,5826.77 3651.54,5826.77 3651.54,5905.51 2694.84,5905.51 2694.84,5826.77 ; 3903.38,90 3903.38,3510 3980,3510 4695,3510 4695,555 5207.2,555 5207.2,90 3903.38,90 ; 4066,1260 4067,1259 4306,1259 4540,1259 4542,1261 4542,1397 4541,1396 4074,1396 4066,1388 4066,1260 ; 4808.35,3261.26 5855.59,3261.26 5855.59,3418.74 5831.97,3442.36 4831.97,3442.36 4808.35,3418.74 4808.35,3261.26 ; 4965,900 5846.81,900 5846.81,1900.75 4965,1900.75 4965,900 ; 5478.94,4779.13 5478.94,5031.1 5497.83,5050 5900,5050 5911.02,5038.98 5911.02,4771.02 5895,4755 5503.07,4755 5478.94,4779.13 ; 5586.61,2393.7 5881.89,2393.7 5881.89,2937.01 5874.02,2944.88 5803.15,2944.88 5661.42,2944.88 5590.55,2944.88 5586.61,2940.95 5586.61,2393.7
  text "120-VAC ONLY" at 35.43,5397.64 h72.83
  text "L1       G        N       N/C       C" at 472.44,5224.41 h72.83 r270
  text "DC BUS CAP" at 4715,4930 h120
  text "GND" at 5510.43,4877.56 h100
  text "ISOLATED INPUT" at 783.46,4433.07 h80
  text "SYSTEM POWER" at 2870,4425 h100
  text "1          2         3         4         5" at 464.57,4129.92 h72.83 r270
  text "3V3" at 1610.24,3755.91 h72.83
  text "+15V" at 2023.62,3755.91 h72.83
  text "WAIT 5 MINUTES" at 5056.38,3375.43 h90
  text "BEFORE HANDLING BOARD" at 4843.78,3292.76 h90
  text "LOW VOLTAGE CONTROL" at 216.54,2881.89 h100
  text "W" at 4275,2855 h72.83
  text "W OUT" at 5602.36,2850.39 h100
  text "3V3 ACTIVE" at 74.8,2799.21 h50
  text "RESET" at 988.19,2716.54 h90
  text "V OUT" at 5610.24,2657.48 h100
  text "+15V ACTIVE" at 74.8,2637.8 h50
  text "PWM ACTIVE" at 74.8,2480.31 h50
  text "PHASE W" at 2813.5,2452.76 h72.83
  text "U OUT" at 5618.11,2444.88 h100
  text "OUTPUT VOLTAGE MONITORING" at 4880,1935 h72.83
  text "GATE DRIVERS" at 2645,1850 h100 r90
  text "V" at 4285,1740 h72.83
  text "MOSFETs" at 4094,1287 h100
  text "CURRENT SENSE AMPLIFICATION" at 645.67,1259.84 h50
  text "PHASE V" at 2813.5,1228.35 h72.83
  text "U" at 4290,575 h72.83
  text "TIDA-01353" at 1654.17,343.35 h108.27
  text "PHASE U" at 2813.5,133.86 h72.83
  text "CURRENT SENSE" at 4040,110 h70
  text "TEMP SENSE" at 4710,110 h70
  text ".Layer_Name" at 577,-858.49 h60
Bottom Overlay:
  text ".Layer_Name" at 577,-858.49 h60
Top Paste:
  text ".Layer_Name" at 577,-858.49 h60
Bottom Paste:
  text ".Layer_Name" at 577,-858.49 h60
Top Solder:
  text ".Layer_Name" at 577,-858.49 h60
  text ".Layer_Name" at 577,-858.49 h60
Bottom Solder:
  text ".Layer_Name" at 577,-858.49 h60
Drill Guide:
  text ".Layer_Name" at 577,-858.49 h60
M1 Board Outline:
  lines w10: 0,3450 0,0 ; 0,0 0,6000 6000,6000 6000,0 0,0
  text ".Layer_Name" at 577,-858.49 h60
M2 Board Dimensions:
  rectangle: 125,-400 500,-275
  rectangle: 0,-275 125,-150
  lines w7: 0,-275 1000,-275 ; 125,-400 125,-150 ; 250,-400 250,-150 ; 500,-400 500,-150 ; 750,-400 750,-150 ; 0,-400 0,-150 1000,-150 1000,-400 0,-400
  text ".Layer_Name" at 577,-858.49 h60
M3 3D STEP Top:
  text ".Layer_Name" at 577,-858.49 h60
M4 3D STEP Bottom:
  text ".Layer_Name" at 577,-858.49 h60
M5 Assembly Top:
  lines w10: -292,-930.17 6308,-930.17 ; -292,-726.83 6310,-726.83 ; -292,-523.5 -292,-1133.5 3713,-1133.5 6310,-1133.5 6310,-523.5 -291.5,-523.5 -291.5,-1133.5 1284,-1133.5 ; 2173,-1133.5 2173,-523.5 ; 3440,-726.83 3440,-523.5 ; 4280,-726.83 4280,-523.5 ; 4902,-1140 4902,-937.17
  text "COMPONENTS MARKED 'DNP' SHOULD NOT BE POPULATED." at 1153.5,-318.5 h60
  text "ASSEMBLY VARIANT:" at 1153,-434 h60
  text ".VariantName" at 2189,-434 h60
  text "PCB VIEWED FROM TOP SIDE" at -228.5,-655.67 h60
  text "BOARD #:" at 2248,-655.67 h60
  text ".PRJ_Number" at 2793.5,-655.67 h60
  text "REV:" at 3638,-655.67 h60
  text ".PCB_Rev" at 3929.5,-655.67 h60
  text "SVN REV:" at 4476,-655.67 h60
  text ".VersionControl_RevNumber" at 4982,-655.67 h60
  text "TID #:" at 2248,-859 h60
  text ".TID" at 2793.5,-859 h60
  text "PLOT NAME =" at -228.5,-1064.34 h60
  text ".plot_File_Name" at 577,-1064.34 h60
  text "GENERATED    :" at 2250,-1064.34 h60
  text ".Print_Date" at 3119.5,-1064.34 h60
  text ".Print_Time" at 3848.5,-1064.34 h60
  text "TEXAS INSTRUMENTS" at 5113,-1064.34 h60
M6 Assembly Bottom:
  lines w10: -292.5,-727.33 6309.5,-727.33 ; -290.5,-930.67 6309.5,-930.67 ; 1115.5,-1140.5 1115.5,-937.67 ; 1737.5,-727.33 1737.5,-524 ; 2577.5,-727.33 2577.5,-524 ; 3844.5,-1134 3844.5,-524 ; 4733.5,-1134 6309,-1134 6309,-524 -292.5,-524 -292.5,-1134 2304.5,-1134 6309.5,-1134 6309.5,-524
  text "COMPONENTS MARKED 'DNP' SHOULD NOT BE POPULATED." at 6102,-318 h60
  text ".VariantName" at 5058,-434 h60
  text "ASSEMBLY VARIANT:" at 6097,-434 h60
  text ".VersionControl_RevNumber" at 1035.5,-656.17 h60
  text "SVN REV:" at 1541.5,-656.17 h60
  text ".PCB_Rev" at 2088,-656.17 h60
  text "REV:" at 2379.5,-656.17 h60
  text ".PRJ_Number" at 3224,-656.17 h60
  text "BOARD #:" at 3769.5,-656.17 h60
  text "PCB VIEWED FROM BOTTOM SIDE" at 6246,-656.17 h60
  text ".TID" at 3224,-859.5 h60
  text "TID #:" at 3769.5,-859.5 h60
  text "TEXAS INSTRUMENTS" at 904.5,-1064.84 h60
  text ".Print_Time" at 2169,-1064.84 h60
  text ".Print_Date" at 2898,-1064.84 h60
  text "GENERATED    :" at 3767.5,-1064.84 h60
  text ".plot_File_Name" at 5440.5,-1064.84 h60
  text "PLOT NAME =" at 6246,-1064.84 h60
M9 Title Sheet:
  drawing of 57 lines, arcs and shapes, not listed
  text "1" at 739.84,8036.5 h70
  text "2" at 3235.5,8036.5 h70
  text "3" at 5724.84,8036.5 h70
  text "4" at 8231.51,8036.5 h70
  text "5" at 10730.5,8036.5 h70
  text "6" at 13235.5,8036.5 h70
  text "A" at -416.5,6893.5 h70
  text "A" at 14383.5,6893.5 h70
  text "B" at -416.5,4513.5 h70
  text "B" at 14383.5,4513.5 h70
  text "C" at -416.5,2138.5 h70
  text "C" at 14383.5,2138.5 h70
  text "PROJECT TITLE:" at 11343.5,277.5 h45
  text "TIDA-01353" at 11393.5,144.17 h70
  text "DESIGNED FOR:" at 11343.5,-23.5 h45
  text ".PRJ_Customer" at 11393.5,-163.5 h70
  text "D" at -416.5,-231.5 h70
  text "D" at 14383.5,-231.5 h70
  text "FILE NAME:" at 11343.5,-323.5 h45
  text ".PCB_File_Name_No_Path" at 11393.5,-443.5 h70
  text "Texas Instruments (TI) and/or its licensors do not warrant the accuracy or completeness of this specification" at 6374,-605.34 h45
  text "ENGINEER:" at 11343.5,-613.5 h45
  text "LAYOUT BY:" at 12848.5,-613.5 h45
  text "or any information contained therein. TI and/or its licensors do not warrant that this design will meet" at 6329.01,-718 h45
  text "Brian Dempsey" at 11393.5,-768.49 h70
  text ".PCB_Layout" at 12899,-768.49 h70
  text "the specifications, will be suitable for your application or fit for any particular purpose, or will operate in" at 6329.01,-830.67 h45
  text ".Layer_Name" at 577,-858.49 h60
  text "ALTIUM DESIGNER VERSION:" at 12848.5,-923.5 h45
  text "an implementation. TI and/or its licensors do not warrant that the design is production worthy. You should" at 6329.01,-943.33 h45
  text "completely validate and test your design implementation to confirm the system functionality for your application." at 6374,-1056 h45
  text ".print_Scale" at 11393.5,-1056.83 h70
  text ".Application_BuildNumber" at 12899,-1056.83 h70
  text "1" at 739.84,-1263.5 h70
  text "2" at 3235.5,-1263.5 h70
  text "3" at 5724.84,-1263.5 h70
  text "4" at 8231.51,-1263.5 h70
  text "5" at 10730.5,-1263.5 h70
  text "6" at 13235.5,-1263.5 h70
M10 Fab Notes:
  drawing of 173 lines, arcs and shapes, not listed
  text "DESIGN INFORMATION" at 12378.02,6201 h60
  text "MIN. TRACK WIDTH:" at 11733.46,6021 h60
  text "8" at 12829.7,6021 h60
  text "MIL" at 12984.46,6021 h60
  text "MIN. CLEARANCE:" at 11733.46,5889 h60
  text "0.2" at 12769.7,5889 h60
  text "mm" at 12984.46,5889 h60
  text "MIN. VIA PAD SIZE:" at 11733.46,5757 h60
  text "22" at 12799.71,5757 h60
  text "MIL" at 12984.46,5757 h60
  text "0.15mm (6MIL)" at 12428.46,5615.29 h60
  text "MINIMUM ANNULAR RING" at 11404.23,5611 h60
  text "EXTERNAL" at 13136.46,5611 h60
  text "PER" at 11604.23,5493 h60
  text "IPC-D-275 CLASS 2 LEVEL C" at 11824.23,5493 h60
  text "MIL, HOLES" at 13312.46,5380.71 h60
  text "+/-" at 12920,5380 h60
  text "+/-" at 13774,5380 h60
  text "REGISTRATION TOLERANCES:" at 11404.23,5375 h60
  text "METAL" at 12604,5375 h60
  text "5" at 13180.2,5375 h60
  text "3" at 14013.2,5375 h60
  text "MIL" at 14129.46,5375 h60
  text "+/-" at 13774,5262 h60
  text "HOLE SIZE TOLERANCE (UNLESS OTHERWISE SPECIFIED):" at 11404.23,5257 h60
  text "3" at 14013.2,5257 h60
  text "MIL" at 14129.46,5257 h60
  text "MATERIAL:" at 11329.46,5047.54 h60
  text "FR-4 High Tg" at 12315.9,4907.21 h60
  text "FR-408" at 11750.46,4898.64 h60
  text "OTHER" at 13238.46,4898.64 h60
  text "X" at 12161,4895 h60
  text "62 MIL (1.6mm) +/-10%" at 12070.56,4735.92 h60
  text "THICKNESS:" at 11404.23,4731.64 h60
  text "X" at 11942.4,4731.64 h60
  text "OTHER" at 13355.46,4731.64 h60
  text "TOLERANCE:" at 11404.23,4573.64 h60
  text "X" at 12243.53,4573.64 h60
  text "ANSI IPC-6012 TYPE 3 CLASS 2" at 12430.48,4573.64 h60
  text "OTHER +/-" at 12430.46,4417.64 h60
  text "BOW & TWIST:" at 11404.23,4260.64 h60
  text "X" at 12243.53,4260.64 h60
  text "ANSI IPC-6012 TYPE 3 CLASS 2" at 12430.48,4260.64 h60
  text "OTHER +/-" at 12430.46,4102.13 h60
  text "DRILLING:" at 11329.46,3963.64 h60
  text "REFERENCE:" at 11404.23,3846.64 h60
  text "X" at 12052.46,3846.64 h60
  text "AS SHOWN" at 12239.46,3846.64 h60
  text "X" at 12953.46,3846.64 h60
  text "NC_DRILL FILES" at 13090.46,3846.64 h60
  text "PTH COPPER THICKNESS:" at 11404.23,3688.64 h60
  text "X" at 12534.46,3688.64 h60
  text "20-30 um" at 12671.46,3688.64 h60
  text "OTHER" at 13388.46,3688.64 h60
  text "BOARD FINISH:" at 11329.46,3529.64 h60
  text "SILKSCREEN:" at 11484.68,3411.64 h60
  text "X" at 12433.46,3411.64 h60
  text "TOP" at 12559.46,3411.64 h60
  text "X" at 12943.46,3411.64 h60
  text "BOTTOM" at 13070.46,3411.64 h60
  text "SILKSCREEN COLOR:" at 11484.68,3244.64 h60
  text "WHITE" at 12559.46,3244.64 h60
  text "OTHER" at 13070.46,3244.64 h60
  text "X" at 12417.32,3232.28 h60
  text "X" at 12562.99,3094.49 h60
  text "GREEN" at 12690.46,3085.44 h60
  text "OTHER" at 13308.46,3085.44 h60
  text "SOLDER RESIST COLOR:" at 11484.68,3074.64 h60
  text "X" at 13169.72,2927.25 h60
  text "MATTE" at 12690.46,2915.44 h60
  text "SEMI-GLOSS" at 13308,2914.8 h60
  text "IMMERSION GOLD (ENIG)" at 12390.46,2726.92 h60
  text "ENEPIG" at 13728,2723.64 h60
  text "SURFACE FINISH:" at 11329.46,2722.64 h60
  text "X" at 12203.51,2722.64 h60
  text "IMM. TIN/SILVER OR EQUIV" at 11659,2565.64 h60
  text "OTHER" at 13090.46,2565.64 h60
  text "ARRAY/PANEL:" at 11329.46,2386.64 h60
  text "CUT AND TRIM PER M1 BOARD OUTLINE" at 12390.46,2382.35 h60
  text "N.C. ROUTE" at 12390.46,2230.64 h60
  text "X" at 13069.46,2230.64 h60
  text "V. SCORE" at 13256.46,2230.64 h60
  text "CERTIFICATION:" at 11329.46,2093.64 h60
  text "MATERIALS AND WORKMANSHIP FOR ALL PCBS" at 12054.46,2093.64 h60
  text "TO MEET OR EXCEED THE REQUIREMENTS OF:" at 12054.46,1995.64 h60
  text "X" at 11680.96,1859.13 h60
  text "ANSI IPC-A-600F CLASS ->" at 11819.96,1859.13 h60
  text "X" at 13459.02,1859.13 h60
  text "2" at 13577.96,1859.14 h60
  text "1" at 13262.96,1857.64 h60
  text "3" at 13931.96,1857.64 h60
  text "X" at 12495.02,1699.64 h60
  text "RoHS" at 12631.96,1699.64 h60
  text "OTHER" at 13276.36,1699.64 h60
  text "PER ORDER" at 13673.42,1699.64 h60
  text "ALL BOARDS MUST MEET OR EXCEED UL94-V0 REQUIREMENTS." at 11357,1534 h60
  text "PCB MUST BEAR THE UL94V-0 UL REGISTERED MATERIAL ID NUMBER" at 11357,1414 h60
  text "ADDITIONAL REQUIREMENTS:" at 11329.46,1240.64 h60
  text "MICROSECTION:" at 11404.23,1125.64 h60
  text "YES" at 12309.96,1125.64 h60
  text "REQUIRED" at 13171.46,969.49 h60
  text "BARE BOARD ELEC. TEST:" at 11404.23,966.64 h60
  text "NONE" at 12709.96,966.64 h60
  text "X" at 13044.46,966.64 h60
  text "PER ORDER" at 13763.46,966.64 h60
  text ".Layer_Name" at 577,-858.49 h60
M11 Gerber Information:
  lines w10: -292,-930.17 6308,-930.17 ; -292,-726.83 6310,-726.83 ; -292,-523.5 -292,-1133.5 3713,-1133.5 6310,-1133.5 6310,-523.5 -291.5,-523.5 -291.5,-1133.5 1284,-1133.5 ; 2173,-1133.5 2173,-523.5 ; 3440,-726.83 3440,-523.5 ; 4280,-726.83 4280,-523.5 ; 4902,-1140 4902,-937.17
  text "ALL ARTWORK VIEWED FROM TOP SIDE" at -228.5,-655.67 h60
  text "BOARD #:" at 2248,-655.67 h60
  text ".PRJ_Number" at 2793.5,-655.67 h60
  text "REV:" at 3638,-655.67 h60
  text ".PCB_Rev" at 3929.5,-655.67 h60
  text "SVN REV:" at 4476,-655.67 h60
  text ".VersionControl_RevNumber" at 4982,-655.67 h60
  text "LAYER NAME =" at -228.5,-858.49 h60
  text "TID #:" at 2248,-859 h60
  text ".TID" at 2793.5,-859 h60
  text "PLOT NAME =" at -228.5,-1064.34 h60
  text ".plot_File_Name" at 577,-1064.34 h60
  text "GENERATED    :" at 2250,-1064.34 h60
  text ".Print_Date" at 3119.5,-1064.34 h60
  text ".Print_Time" at 3848.5,-1064.34 h60
  text "TEXAS INSTRUMENTS" at 5113,-1064.34 h60
M12 Stackup:
  drawing of 191 lines, arcs and shapes, not listed
  text "Layer" at 9742.5,7502.5 h60
  text "Name" at 10152.41,7502.5 h60
  text "Material" at 11082.16,7502.5 h60
  text "Thickness" at 11941.92,7502.5 h60
  text "Constant" at 12591.76,7502.5 h60
  text "Board Layer Stack" at 13161.62,7502.5 h60
  text "1" at 9742.5,7382.5 h60
  text "Top Overlay" at 10152.41,7382.5 h60
  text "2" at 9742.5,7262.5 h60
  text "Top Solder" at 10152.41,7262.5 h60
  text "Solder Resist" at 11082.16,7262.5 h60
  text "0.40mil" at 11941.92,7262.5 h60
  text "3.5" at 12591.76,7262.5 h60
  text "3" at 9742.5,7142.5 h60
  text "Top Layer" at 10152.41,7142.5 h60
  text "Copper" at 11082.16,7142.5 h60
  text "2.80mil" at 11941.92,7142.5 h60
  text "4" at 9742.5,7022.5 h60
  text "Dielectric1" at 10152.41,7022.5 h60
  text "FR-4 High TG" at 11082.16,7022.5 h60
  text "56.00mil" at 11941.92,7022.5 h60
  text "4.8" at 12591.76,7022.5 h60
  text "5" at 9742.5,6902.5 h60
  text "Bottom Layer" at 10152.41,6902.5 h60
  text "Copper" at 11082.16,6902.5 h60
  text "2.80mil" at 11941.92,6902.5 h60
  text "6" at 9742.5,6782.5 h60
  text "Bottom Solder" at 10152.41,6782.5 h60
  text "Solder Resist" at 11082.16,6782.5 h60
  text "0.40mil" at 11941.92,6782.5 h60
  text "3.5" at 12591.76,6782.5 h60
  text "7" at 9742.5,6662.5 h60
  text "Bottom Overlay" at 10152.41,6662.5 h60
  text ".Layer_Name" at 577,-858.49 h60
M13 Component Bodies Top:
  text ".Layer_Name" at 577,-858.49 h60
M14 Component Bodies Bottom:
  text ".Layer_Name" at 577,-858.49 h60
M15 Courtyards Top:
  text ".Layer_Name" at 577,-858.49 h60
M16 Courtyards Bottom:
  text ".Layer_Name" at 577,-858.49 h60
Drill Drawing:
  circle w10: c6163.49,1381.38 r22.97
  circle w10: c6163.49,1381.38 r38.28
  circle w10: c6163.49,864.61 r38.28
  lines w10: 6125.21,1591.91 6201.77,1591.91 6163.49,1515.35 6125.21,1591.91 ; 6125.21,1764.17 6201.77,1764.17 6163.49,1687.61 6125.21,1764.17 ; 6125.21,1859.86 6201.77,1859.86 6201.77,1936.42 6125.21,1936.42 6125.21,1859.86 ; 6125.21,2070.4 6163.49,2032.12 6201.77,2070.4 6163.49,2108.68 6125.21,2070.4 ; 6125.21,2223.52 6144.35,2223.52 6163.49,2204.38 6182.63,2223.52 6201.77,2223.52 6182.63,2242.66 6201.77,2261.79 6182.63,2261.79 6163.49,2280.93 6144.35,2261.79 6125.21,2261.79 6144.35,2242.66 6125.21,2223.52 ; 6125.21,2568.03 6144.35,2568.03 6163.49,2548.89 6182.63,2568.03 6201.77,2568.03 6182.63,2587.17 6201.77,2606.31 6182.63,2606.31 6163.49,2625.45 6144.35,2606.31 6125.21,2606.31 6144.35,2587.17 6125.21,2568.03 ; 6125.21,2721.14 6201.77,2721.14 6201.77,2797.7 6125.21,2797.7 6125.21,2721.14 ; 6125.21,2912.54 6144.35,2912.54 6144.35,2893.4 6182.63,2893.4 6182.63,2912.54 6201.77,2912.54 6201.77,2950.82 6182.63,2950.82 6182.63,2969.96 6144.35,2969.96 6144.35,2950.82 6125.21,2950.82 6125.21,2912.54 ; 6125.21,3065.66 6163.49,3084.8 6201.77,3065.66 6182.63,3103.94 6201.77,3142.21 6163.49,3123.07 6125.21,3142.21 6144.35,3103.94 6125.21,3065.66 ; 6140.52,1576.6 6186.45,1576.6 6163.49,1530.66 6140.52,1576.6 ; 6140.52,1875.18 6186.45,1875.18 6186.45,1921.11 6140.52,1921.11 6140.52,1875.18 ; 6140.52,2231.17 6152,2231.17 6163.49,2219.69 6174.97,2231.17 6186.45,2231.17 6174.97,2242.66 6186.45,2254.14 6174.97,2254.14 6163.49,2265.62 6152,2254.14 6140.52,2254.14 6152,2242.66 6140.52,2231.17 ; 6140.52,2920.2 6152,2920.2 6152,2908.71 6174.97,2908.71 6174.97,2920.2 6186.45,2920.2 6186.45,2943.16 6174.97,2943.16 6174.97,2954.65 6152,2954.65 6152,2943.16 6140.52,2943.16 6140.52,2920.2
  lines w12: 6057.01,774.65 10535.11,774.65 ; 6057.01,3186.24 10535.11,3186.24 ; 6525.21,602.4 6525.21,3358.49 ; 6985.31,602.4 6985.31,3358.49 ; 7867.49,602.4 7867.49,3358.49 ; 8226.6,602.4 8226.6,3358.49 ; 8746.51,602.4 8746.51,3358.49 ; 9750.13,602.4 9750.13,3358.49 ; 6057.01,602.4 10535.11,602.4 10535.11,3358.49 6057.01,3358.49 6057.01,602.4
  text "Symbol" at 6160.36,3237.91 h99.72
  text "Quantity" at 6576.89,3237.91 h99.72
  text "Finished Hole Size" at 7036.98,3237.91 h99.72
  text "Plated" at 7919.16,3237.91 h99.72
  text "Hole Type" at 8278.28,3237.91 h99.72
  text "Drill Layer Pair" at 8798.18,3237.91 h99.72
  text "Hole Tolerance" at 9801.81,3237.91 h99.72
  text "165" at 6576.89,3065.66 h83.1
  text "10.00mil (0.254mm)" at 7036.98,3065.66 h83.1
  text "PTH" at 7919.16,3065.66 h83.1
  text "Round" at 8278.28,3065.66 h83.1
  text "Top Layer - Bottom Layer" at 8798.18,3065.66 h83.1
  text "3" at 6576.89,2893.4 h83.1
  text "27.56mil (0.700mm)" at 7036.98,2893.4 h83.1
  text "PTH" at 7919.16,2893.4 h83.1
  text "Round" at 8278.28,2893.4 h83.1
  text "Top Layer - Bottom Layer" at 8798.18,2893.4 h83.1
  text "6" at 6576.89,2721.14 h83.1
  text "33.46mil (0.850mm)" at 7036.98,2721.14 h83.1
  text "PTH" at 7919.16,2721.14 h83.1
  text "Round" at 8278.28,2721.14 h83.1
  text "Top Layer - Bottom Layer" at 8798.18,2721.14 h83.1
  text "6" at 6576.89,2548.89 h83.1
  text "35.43mil (0.900mm)" at 7036.98,2548.89 h83.1
  text "PTH" at 7919.16,2548.89 h83.1
  text "Round" at 8278.28,2548.89 h83.1
  text "Top Layer - Bottom Layer" at 8798.18,2548.89 h83.1
  text "14" at 6576.89,2376.63 h83.1
  text "40.00mil (1.016mm)" at 7036.98,2376.63 h83.1
  text "PTH" at 7919.16,2376.63 h83.1
  text "Round" at 8278.28,2376.63 h83.1
  text "Top Layer - Bottom Layer" at 8798.18,2376.63 h83.1
  text "D" at 6127.98,2366.64 h76.56
  text "10" at 6576.89,2204.38 h83.1
  text "40.16mil (1.020mm)" at 7036.98,2204.38 h83.1
  text "PTH" at 7919.16,2204.38 h83.1
  text "Round" at 8278.28,2204.38 h83.1
  text "Top Layer - Bottom Layer" at 8798.18,2204.38 h83.1
  text "4" at 6576.89,2032.12 h83.1
  text "41.34mil (1.050mm)" at 7036.98,2032.12 h83.1
  text "PTH" at 7919.16,2032.12 h83.1
  text "Round" at 8278.28,2032.12 h83.1
  text "Top Layer - Bottom Layer" at 8798.18,2032.12 h83.1
  text "4" at 6576.89,1859.86 h83.1
  text "43.31mil (1.100mm)" at 7036.98,1859.86 h83.1
  text "PTH" at 7919.16,1859.86 h83.1
  text "Round" at 8278.28,1859.86 h83.1
  text "Top Layer - Bottom Layer" at 8798.18,1859.86 h83.1
  text "31" at 6576.89,1687.61 h83.1
  text "49.21mil (1.250mm)" at 7036.98,1687.61 h83.1
  text "PTH" at 7919.16,1687.61 h83.1
  text "Round" at 8278.28,1687.61 h83.1
  text "Top Layer - Bottom Layer" at 8798.18,1687.61 h83.1
  text "2" at 6576.89,1515.35 h83.1
  text "55.12mil (1.400mm)" at 7036.98,1515.35 h83.1
  text "PTH" at 7919.16,1515.35 h83.1
  text "Round" at 8278.28,1515.35 h83.1
  text "Top Layer - Bottom Layer" at 8798.18,1515.35 h83.1
  text "4" at 6576.89,1343.1 h83.1
  text "59.06mil (1.500mm)" at 7036.98,1343.1 h83.1
  text "PTH" at 7919.16,1343.1 h83.1
  text "Round" at 8278.28,1343.1 h83.1
  text "Top Layer - Bottom Layer" at 8798.18,1343.1 h83.1
  text "4" at 6576.89,1170.84 h83.1
  text "62.99mil (1.600mm)" at 7036.98,1170.84 h83.1
  text "PTH" at 7919.16,1170.84 h83.1
  text "Round" at 8278.28,1170.84 h83.1
  text "Top Layer - Bottom Layer" at 8798.18,1170.84 h83.1
  text "C" at 6127.98,1160.85 h76.56
  text "2" at 6576.89,998.58 h83.1
  text "78.74mil (2.000mm)" at 7036.98,998.58 h83.1
  text "PTH" at 7919.16,998.58 h83.1
  text "Round" at 8278.28,998.58 h83.1
  text "Top Layer - Bottom Layer" at 8798.18,998.58 h83.1
  text "+/-3.94mil" at 9801.81,998.58 h83.1
  text "B" at 6127.98,988.6 h76.56
  text "4" at 6576.89,826.33 h83.1
  text "125.98mil (3.200mm)" at 7036.98,826.33 h83.1
  text "PTH" at 7919.16,826.33 h83.1
  text "Round" at 8278.28,826.33 h83.1
  text "Top Layer - Bottom Layer" at 8798.18,826.33 h83.1
  text "259 Total" at 6576.89,654.07 h83.1
  text ".Layer_Name" at 577,-858.49 h60
M17 Embedded Cavity:
  text ".Layer_Name" at 577,-858.49 h60
M18 Embedded Assembly:
  text ".Layer_Name" at 577,-858.49 h60
M19 Embedded Keepout:
  text ".Layer_Name" at 577,-858.49 h60

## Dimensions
0,0 to 0,6000 on M2 Board Dimensions
0,0 to 6000,0 on M2 Board Dimensions
0,-400 to 1000,-400 on M2 Board Dimensions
